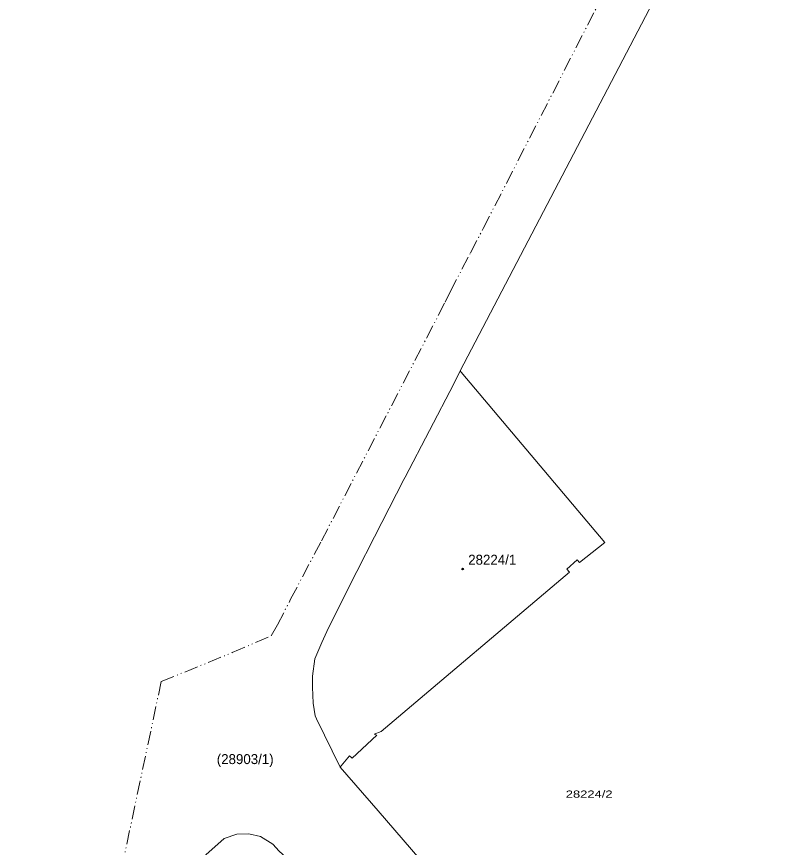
# Model space of a CAD drawing. Extents: x 650553 to 652508, y 239277 to 241647.
# Drawn here: x 650553 to 650830.2, y 240705.5 to 241006.5 of the extents above; entities that cross this region are included whole.
import ezdxf

# ---------------------------------------------------------------- set-up
doc = ezdxf.new("R2010")
doc.units = 0
doc.header["$PDMODE"] = 32
doc.header["$PDSIZE"] = 0.5
doc.linetypes.add('DASH_DOUBLE_DOT', pattern=[9.2, 5, -1.2, 0.3, -1.2, 0.3, -1.2])
for name, color, linetype in [('19', 7, 'Continuous'), ('20', 7, 'Continuous'), ('6', 7, 'Continuous')]:
    doc.layers.add(name, color=color, linetype=linetype)
for name, color, linetype, lineweight in [('3', 7, 'Continuous', 13), ('5', 7, 'Continuous', 13), ('52', 7, 'DASH_DOUBLE_DOT', 13)]:
    doc.layers.add(name, color=color, linetype=linetype, lineweight=lineweight)

msp = doc.modelspace()

# ---------------------------------------------------------------- linework, layer by layer
at = {"layer": '3'}
for points in [[(650713.699, 240878.214), (650830.17, 241100.87)], [(650670.237, 240734.531), (650661.737, 240752.054), (650661.157, 240753.175), (650660.48, 240757.757), (650660.235, 240763.586), (650660.265, 240767.607), (650661.108, 240773.842), (650663.645, 240779.794), (650665.978, 240785.033), (650676.324, 240805.506), (650682.714, 240818.069), (650693.313, 240838.77), (650693.871, 240839.711), (650711.493, 240873.458), (650713.699, 240878.214)], [(650806.33, 240577.79), (650765.444, 240626.293), (650746.606, 240648.49), (650731.529, 240665.947), (650726.049, 240672.268), (650724.783, 240671.099), (650711.274, 240687.205), (650684, 240718.73), (650670.237, 240734.531)], [(650696.1, 240649.407), (650688.549, 240657.818), (650651.503, 240701.065), (650648.168, 240704.201), (650645.87, 240706.648), (650641.372, 240709.429), (650637.2, 240710.453), (650632.875, 240710.256), (650628.245, 240708.762), (650621.636, 240702.791), (650619.734, 240698.95), (650618.767, 240694.523), (650619.141, 240689.967), (650620.905, 240685.179), (650625.93, 240678.961), (650663.001, 240636.096), (650670.4, 240627.253)]]:
    msp.add_lwpolyline(points, dxfattribs=at)
at = {"layer": '5'}
msp.add_lwpolyline([(650670.237, 240734.531), (650670.653, 240735.031), (650673.707, 240738.7), (650674.667, 240737.833), (650683.581, 240746.193), (650682.62, 240746.525), (650685.176, 240747.488), (650753.437, 240805.21), (650752.452, 240806.28), (650756.124, 240809.736), (650757.059, 240808.691), (650766.173, 240815.956), (650714.12, 240877.714), (650713.699, 240878.214)], dxfattribs=at)
at = {"layer": '52'}
for points in [[(650605.404, 240765.589), (650631.18, 240776.077), (650645.317, 240782.152), (650647.534, 240786.107), (650652.296, 240795.405), (650663.455, 240816.552), (650708.292, 240903.006), (650710.188, 240906.79), (650717.498, 240920.924), (650722.084, 240929.73), (650787.671, 241057.451)], [(650605.404, 240765.589), (650575.102, 240622.376), (650564.111, 240019.547), (650563.292, 239912.239), (650561.967, 239831.306), (650558.948, 239635.138), (650557.76, 239590.469), (650555.824, 239499.761), (650555.114, 239481.758), (650553.994, 239393.396), (650554.019, 239393.395), (650553.222, 239318.763), (650553.006, 239301.006), (650586.911, 239277.281)]]:
    msp.add_lwpolyline(points, dxfattribs=at)
at = {"layer": '6'}
msp.add_point((650714.657, 240806.372), dxfattribs=at)

# ---------------------------------------------------------------- texts
at = {"layer": '19'}
for s, p in [('28224/1', (650716.675, 240807.944)), ('(28903/1)', (650625.545, 240735.699))]:
    msp.add_text(s, height=3.6, dxfattribs=at).set_placement(p)
at = {"layer": '20', "width": 1.35}
msp.add_text('28224/2', height=2.6, dxfattribs=at).set_placement((650752.026, 240723.522))

doc.saveas('drawing.dxf')
